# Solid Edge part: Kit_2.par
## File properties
Author: ahadarics
Last saved by: ahadarics
Revision: 76
Sűrűség: 0,000 kg/m^3
Pontosság: 0,990
Username: ahadarics
Dokumentum tartalom típus: 0
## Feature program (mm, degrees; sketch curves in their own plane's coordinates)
base feature "unnamed BaseFeature 1"
thread "unnamed Thread 1"
sketch for "unnamed Hole 1" plane through (-36, -36, 14) normal (0, 0, 1) x-axis (0, 1, 0)
  hole centre (0, 0) bore radius 4.188
hole "unnamed Hole 1" through
sketch for "unnamed Hole 2" plane through (-36, -36, 14) normal (0, 0, 1) x-axis (0, 1, 0)
  hole centre (72, 0) bore radius 4.188
hole "unnamed Hole 2" through
sketch for "unnamed Hole 3" plane through (-36, -36, 14) normal (0, 0, 1) x-axis (0, 1, 0)
  hole centre (72, -72) bore radius 4.188
hole "unnamed Hole 3" through
sketch for "unnamed Hole 4" plane through (-36, -36, 14) normal (0, 0, 1) x-axis (0, 1, 0)
  hole centre (0, -72) bore radius 4.188
hole "unnamed Hole 4" through
pattern "unnamed Pattern 1" of "unnamed Hole 1", "unnamed Hole 2", "unnamed Hole 3", "unnamed Hole 4"
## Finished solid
Body 1: solid body, 294 faces, 719 edges, 443 vertices.
  Faces by surface: plane 138, cylinder 72, swept 60, cone 15, torus 8, spline 1
  Edges by curve: line 421, circle 137, spline 120, ellipse 32, curve on surface 8, intersection 1
Bounding box of the edges (mm; curved faces can reach further): 95.500 x 95.500 x 15.000, from (-47.75, -47.75, 2) to (47.75, 47.75, 17).
Cylindrical faces by radius (mm): R0.2 x48, R0.2017 x2, R0.2018 x2, R2.5 x1, R4.188 x4, R4.283 x1, R4.9 x4, R5.15 x4, R6 x1, R6.75 x4, R21.1047 x1
Conical faces (half-angle, radius in mm at the cone's reference point): 0.5 deg R10 x4, 0.5 deg R13.5 x2, 45 deg R4.185 x4, 45 deg R4.985 x4, 45 deg R6.25 x1
Toroidal faces (ring radius, tube radius in mm): R4.7 r0.2 x8
Planar faces by outward normal: +x 14, +y 13, +z 18, -x 17, -y 14, -z 1, oblique 61
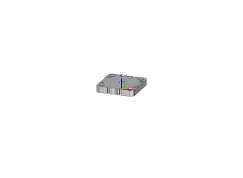
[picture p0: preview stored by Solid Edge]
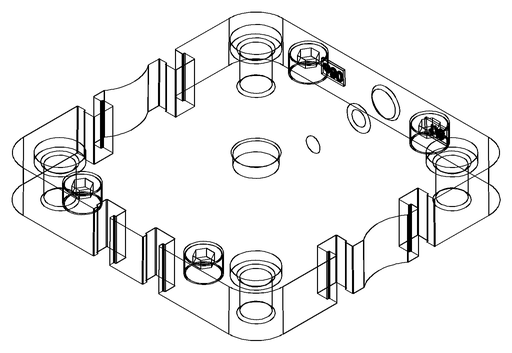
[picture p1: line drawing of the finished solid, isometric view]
